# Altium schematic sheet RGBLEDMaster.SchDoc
size A
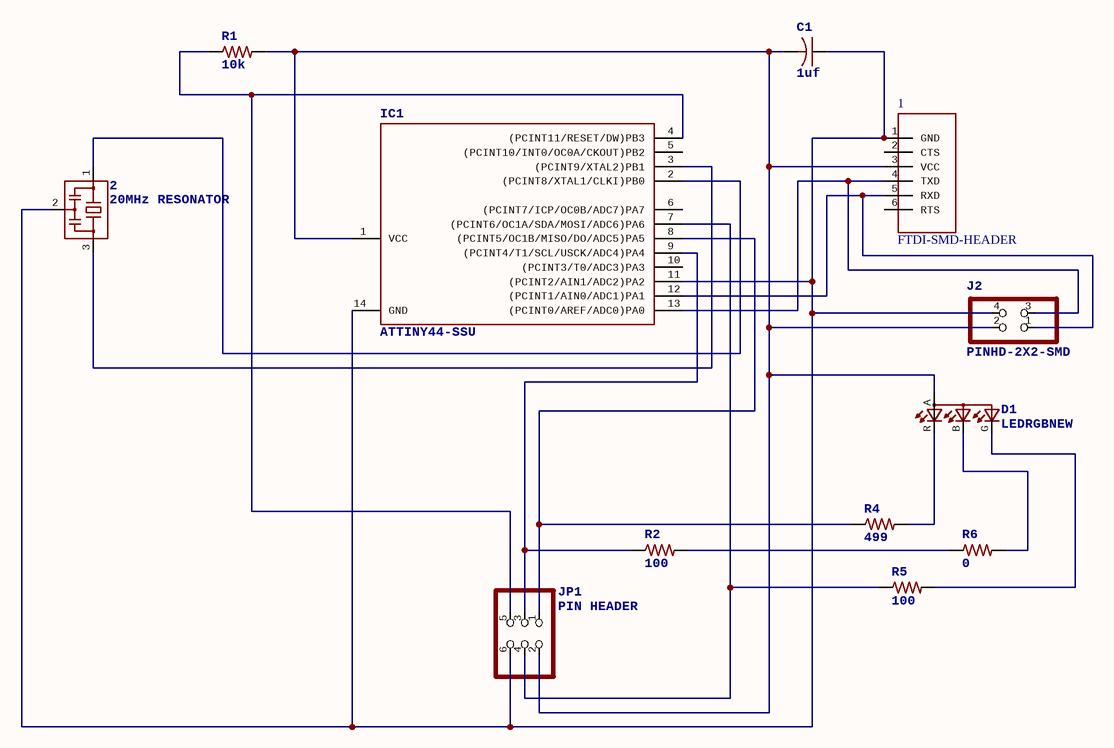
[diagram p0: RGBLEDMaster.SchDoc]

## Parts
1  FTDI-SMD-HEADER  [1X06SMD]
2  20MHz RESONATOR  [EFOBM]
C1  1uf  [C1206]
D1  LEDRGBNEW  [P-LCC-4]
IC1  ATTINY44-SSU  [SOIC14]
J2  PINHD-2X2-SMD  [2X02SMD]
JP1  PIN HEADER  [2X03SMD]
R1  10k  [R1206]
R2  100  [R1206]
R4  499  [R1206]
R5  100  [R1206]
R6  0  [R1206]

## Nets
Net1_1: 1.1(GND) 2.2 C1.1 IC1.11((PCINT2/AIN1/ADC2)PA2) IC1.14(GND) J2.4 JP1.6
Net1_3: 1.3(VCC) C1.2 D1.A(A2) IC1.1(VCC) J2.2 JP1.2 R1.2
Net1_4: 1.4(TXD) IC1.13((PCINT0/AREF/ADC0)PA0) J2.3
Net1_5: 1.5(RXD) IC1.12((PCINT1/AIN0/ADC1)PA1) J2.1
Net2_1: 2.1 IC1.2((PCINT8/XTAL1/CLKI)PB0)
Net2_3: 2.3 IC1.3((PCINT9/XTAL2)PB1)
NetD1_B: D1.B(CBLUE) R6.2
NetD1_G: D1.G(CGREEN) R5.2
NetD1_R: D1.R(CRED) R4.2
NetIC1_4: IC1.4((PCINT11/RESET/DW)PB3) JP1.5 R1.1
NetIC1_7: IC1.7((PCINT6/OC1A/SDA/MOSI/ADC6)PA6) JP1.4 R5.1
NetIC1_8: IC1.8((PCINT5/OC1B/MISO/DO/ADC5)PA5) JP1.1 R4.1
NetIC1_9: IC1.9((PCINT4/T1/SCL/USCK/ADC4)PA4) JP1.3 R2.1
NetR2_2: R2.2 R6.1

Not connected (* = marked no-connect by the designer): 1 2(CTS) 6(RTS); IC1 5((PCINT10/INT0/OC0A/CKOUT)PB2) 6((PCINT7/ICP/OC0B/ADC7)PA7) 10((PCINT3/T0/ADC3)PA3)

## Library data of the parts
2 = RESONATOR
C1 = CAP-US1206
JP1 = PINHD-2X3-SMD
R1 R2 R4-R6 = RES-US1206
